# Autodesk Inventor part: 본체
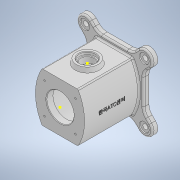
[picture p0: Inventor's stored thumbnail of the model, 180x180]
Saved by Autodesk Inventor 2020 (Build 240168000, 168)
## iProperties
Created: 2022-01
Part Number: 본체
Material: 일반
Document SubType Name: Modeling
Designer: user
Density: 1 g/cm^3
Appearance: 기본값
Mass: 458.999 g
Surface Area: 907.713 cm^2
Volume: 458.999 cm^3
Author: user
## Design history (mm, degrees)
sketch "스케치1"
  geometry: L1 (-45, -45)-(45, -45); L2 (45, -45)-(45, 45); L3 (45, 45)-(-32.942, 45); L4 (-45, 45)-(-45, -45); L5 (-45, -45)-(45, 45); L6 (45, -45)-(-45, 45); A1 r 90 centre (45, 0) between (-32.942, 45) and (-32.942, -45); A2 r 90 centre (-45, 0) between (32.942, -45) and (32.942, 45); 12 further points
  constraints: 12 end point, 10 point on circle, 7 point on line, 6 midpoint, 3 coincident, 3 vertical alignment, 2 centre point, 2 parallel, 1 horizontal, 1 horizontal alignment, 1 perpendicular
  dimensions: "d0" = 90 distance of L4.start L2.end; "d1" = 90 distance of L2.end L1.end
extrude "돌출1" new body sketch "스케치1" stored distance "d5" = 100; taper "d6" = 0 deg
sketch "스케치2"
  geometry: L1 (-53, -53)-(53, -53); L2 (53, -53)-(53, 53); L3 (53, 53)-(-53, 53); L4 (-53, 53)-(-53, -53); L5 (-53, -53)-(53, 53); L6 (53, -53)-(-53, 53); L7 (54.447, -54.447)-(-54.447, 54.447); L8 (65.054, -43.841)-(-43.841, 65.054); L9 (-65.054, 43.841)-(43.841, -65.054); L10 (-54.447, -54.447)-(54.447, 54.447); L11 (-43.841, -65.054)-(65.054, 43.841); L12 (43.841, 65.054)-(-65.054, -43.841); A1 r 15 centre (54.447, -54.447) between (43.841, -65.054) and (65.054, -43.841); A2 r 15 centre (-54.447, 54.447) between (-43.841, 65.054) and (-65.054, 43.841); A3 r 15 centre (-54.447, -54.447) between (-65.054, -43.841) and (-43.841, -65.054); A4 r 15 centre (54.447, 54.447) between (65.054, 43.841) and (43.841, 65.054); A5 r 77 centre (0, 0) between (-42.798, 64.011) and (-64.011, 42.798); A6 r 77 centre (0, 0) between (64.011, 42.798) and (42.798, 64.011); A7 r 77 centre (0, 0) between (-64.011, -42.798) and (-42.798, -64.011); A8 r 77 centre (0, 0) between (42.798, -64.011) and (64.011, -42.798); 9 further points
  constraints: 28 end point, 18 point on circle, 10 point on line, 8 centre point, 8 tangent, 4 midpoint, 4 parallel, 1 coincident, 1 horizontal, 1 perpendicular
  dimensions: "d7" = 106 distance of L3.end L2.end; "d8" = 106 distance of L2.end L1.end; "d10" = 30 diameter of A2; "d11" = 30 diameter of A4
extrude "돌출2" join sketch "스케치2" distance "d12" = 10; taper "d13" = 0 deg
sketch "스케치3"
  geometry: 1 further point
sketch "스케치4"
  geometry: 1 further point
node "작업 평면1"
sketch "스케치5"
  geometry: C1 r 20 at (0, 0); 1 further point
  constraints: 1 centre point, 1 coincident
  dimensions: "d15" = 40 diameter of C1
extrude "돌출3" join sketch "스케치5" stored distance "d16" = 10; taper "d17" = 15 deg
sketch "스케치6"
  geometry: C1 r 25 at (0, 0); 1 further point
  constraints: 1 centre point, 1 coincident
  dimensions: "d18" = 50 diameter of C1
extrude "돌출4" cut sketch "스케치6" distance "d19" = 12; taper "d20" = 0 deg
sketch "스케치7"
  geometry: C1 r 37 at (0, 0); 1 further point
  constraints: 1 centre point, 1 coincident
  dimensions: "d21" = 74 diameter of C1
extrude "돌출5" cut sketch "스케치7" distance "d22" = 86; taper "d23" = 0 deg
sketch "스케치8"
  geometry: C1 r 25 at (0, 0); 1 further point
  constraints: 1 centre point, 1 coincident
  dimensions: "d24" = 50 diameter of C1
extrude "돌출6" cut sketch "스케치8" distance "d25" = 12; taper "d26" = 0 deg
sketch "스케치9"
  geometry: L1 (0, 0)-(-28.284, 28.284); L2 (0, 0)-(40, 0); L3 (0, 0)-(28.284, 28.284); L4 (0, 0)-(40, 0)
  constraints: 8 end point, 2 equal length, 2 horizontal
  dimensions: "d27" = 40 distance of L1.start L1.end; "d28" = 135 deg angle of L2 L1; "d29" = 40 distance of L1.start L3.end; "d30" = 45 deg angle of L4 L3
hole "구멍1" sketch "스케치9" at (-28.284, 28.284), (28.284, 28.284) diameter "d31" = 3.242; stored, may be unused: countersink angle "d35" = 90 deg, drill point angle "d37" = 118 deg; dims "d32" = 8, "d33" = 4, "d34" = 2, "d36" = 10
sketch "스케치10"
  geometry: L1 (0, 0)-(-28.284, 28.284); L2 (0, 0)-(40, 0); L3 (0, 0)-(28.284, 28.284); L4 (0, 0)-(40, 0)
  constraints: 8 end point, 2 equal length, 2 horizontal
  dimensions: "d38" = 40 distance of L1.start L1.end; "d39" = 135 deg angle of L2 L1; "d40" = 40 distance of L1.start L3.end; "d41" = 45 deg angle of L4 L3
hole "구멍2" sketch "스케치10" at (28.284, 28.284), (-28.284, 28.284) diameter "d42" = 3.242; stored, may be unused: countersink angle "d46" = 90 deg, drill point angle "d48" = 118 deg; dims "d43" = 8, "d44" = 4, "d45" = 2, "d47" = 10
sketch "스케치11"
  geometry: A1 r 15 centre (54.447, 54.447) between (65.054, 43.841) and (43.841, 65.054) reference; A2 r 15 centre (-54.447, 54.447) between (-43.841, 65.054) and (-65.054, 43.841) reference; A3 r 15 centre (54.447, -54.447) between (43.841, -65.054) and (65.054, -43.841) reference; A4 r 15 centre (-54.447, -54.447) between (-65.054, -43.841) and (-43.841, -65.054) reference; 5 further points
  constraints: 4 coincident
hole "구멍3" sketch "스케치11" at (54.447, 54.447), (-54.447, 54.447), (54.447, -54.447), (-54.447, -54.447) diameter "d49" = 9; stored, may be unused: countersink angle "d53" = 90 deg, drill point angle "d55" = 0 deg; dims "d50" = 8, "d51" = 18, "d52" = 2, "d54" = 10
sketch "스케치12"
  geometry: C1 r 15 at (0, 0); 1 further point
  constraints: 1 centre point, 1 coincident
  dimensions: "d56" = 30 diameter of C1
extrude "돌출7" cut sketch "스케치12" distance "d57" = 5; taper "d58" = 0 deg
sketch "스케치13"
  geometry: C1 r 15 at (0, 0) reference; C2 r 12 at (0, 0); 1 further point
  constraints: 1 centre point, 1 coincident
  dimensions: "d59" = 24 diameter of C2
extrude "돌출8" cut sketch "스케치13" stored distance "d60" = 5; taper "d61" = 0 deg
chamfer "모따기1" distance "d62" = 1; stored, may be unused: second distance "d63" = 2, angle "d64" = 45 deg
chamfer "모따기2" distance "d65" = 1; stored, may be unused: second distance "d66" = 2, angle "d67" = 45 deg
fillet "모깎기1" dims "d68" = 3
fillet "모깎기2" dims "d69" = 3
fillet "모깎기3" dims "d70" = 3
fillet "모깎기4" dims "d71" = 20
fillet "모깎기5" dims "d72" = 3
node "작업 평면3"
sketch "스케치14"
  geometry: L1 (53, -20)-(53, 20) reference; L2 (23.503, -60)-(37.645, -60) reference; 2 further points
  constraints: 1 other
  dimensions: "d75" = 53 distance from line of L1 point (0, 0); "d76" = 60 distance from line of point (0, 0) L2
feature "엠보싱1" sketch "스케치14" dims "d0" = 90, "d1" = 90, "d77" = 0.5, "d78" = 0
node "솔리드1"
mirror "미러1"
mirror "미러2"
feature "A9D066F2-1C7D-4E18-AEED-F7BC21143FA4" dims "d49" = 9, "d50" = 8, "d51" = 18, "d52" = 2, "d53" = 90 deg, "d54" = 10, "d55" = 0
other parameters: "d9" = 154, "d14" = 53, "d74" = 45
